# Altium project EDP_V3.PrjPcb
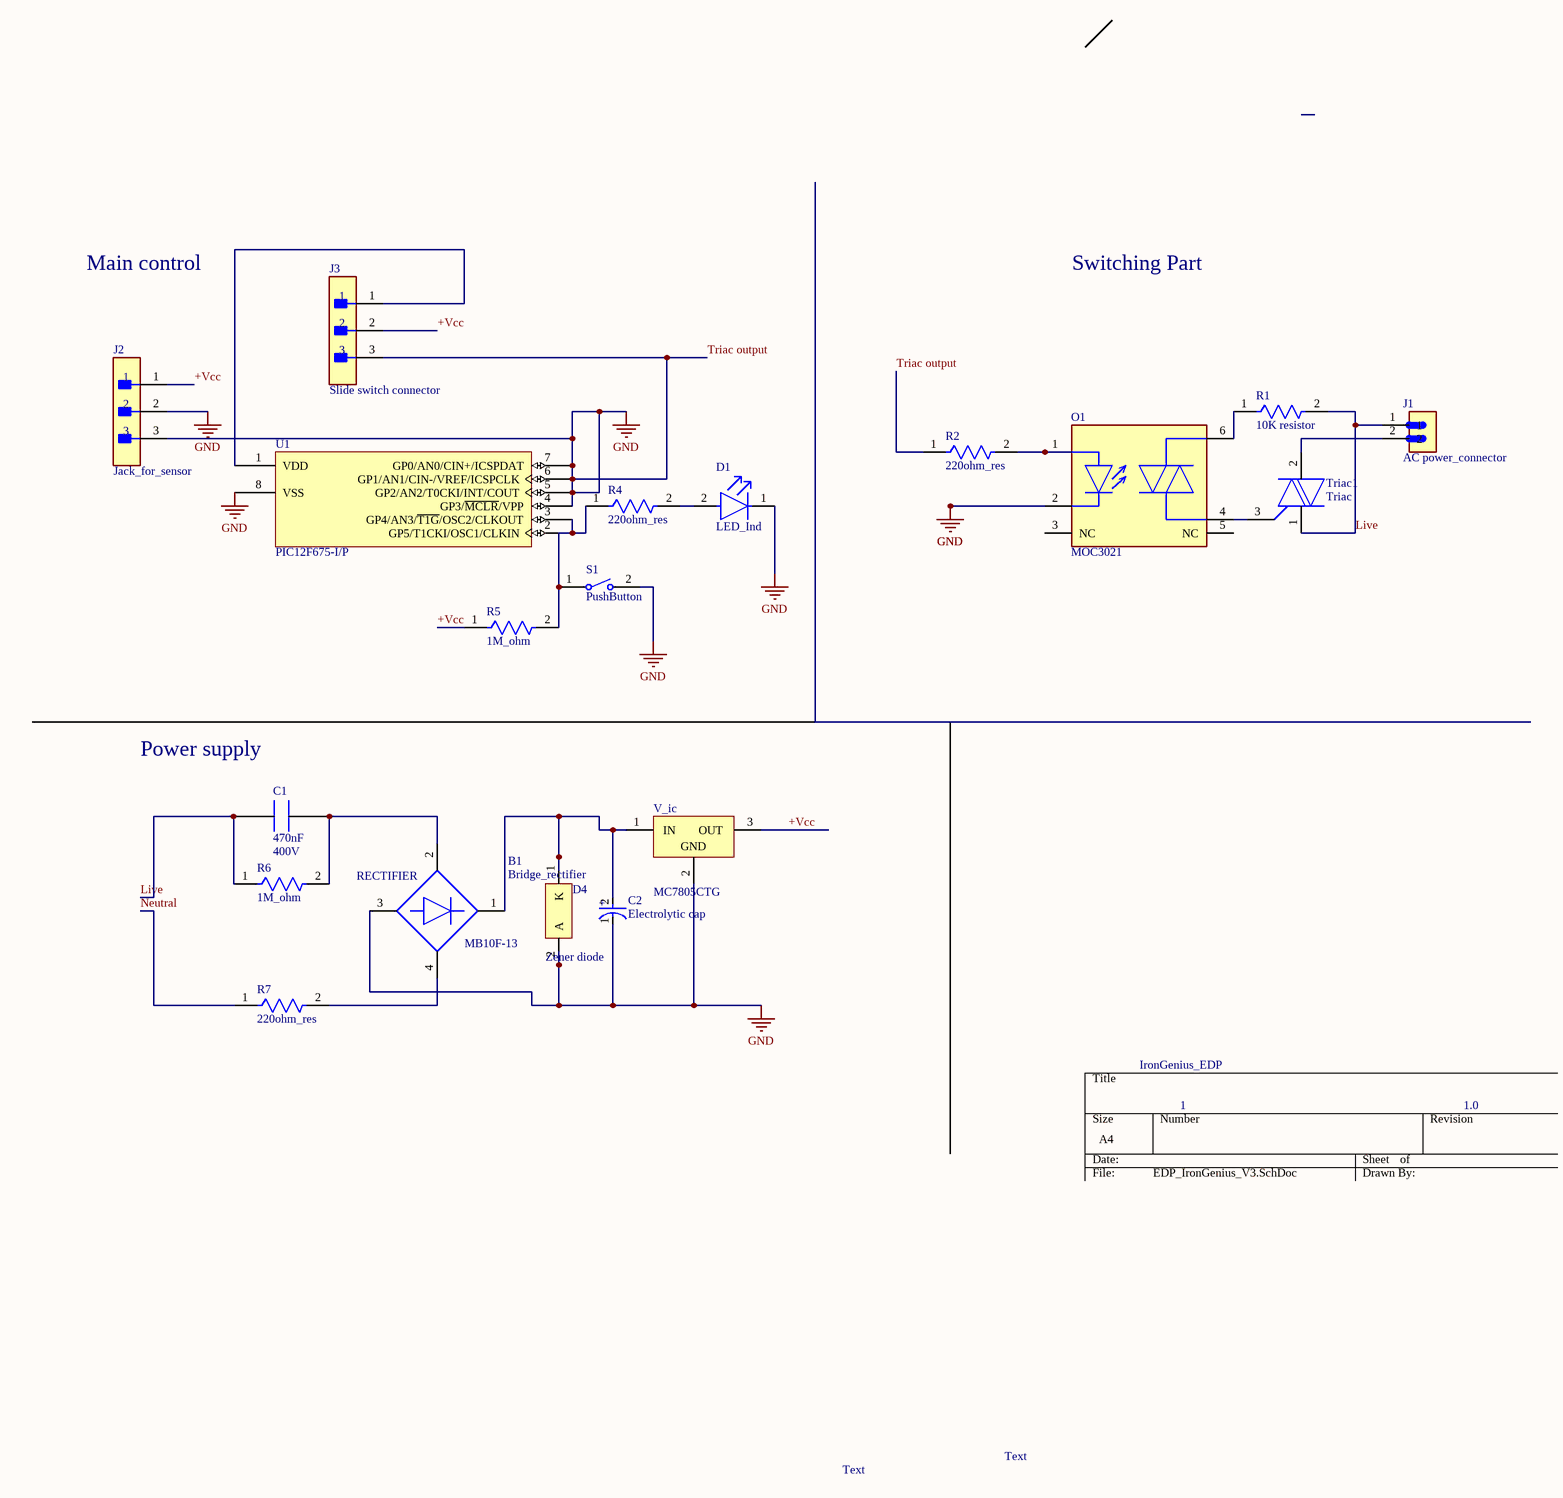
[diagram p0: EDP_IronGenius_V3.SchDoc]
1 sheet, 19 parts. Net scope: global (net labels, ports and power ports of the same name join across sheets).
Board file: EDP_V3.PcbDoc

## Sheet EDP_IronGenius_V3.SchDoc: IronGenius_EDP
size A4; Revision: 1.0; SheetNumber: 1; SheetTotal: 1

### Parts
B1  Bridge_rectifier  Manufacturer Part Number: MB10F-13  Diode Type: RECTIFIER  [Bridge rectifier]
C1  value 470nF  Rated AC Voltage (URac): 400V  [Capacitor 470nF 400V AC]
C2  Electrolytic cap  [Electrolytic cap]
D1  LED_Ind  [LED_ind]
D4  Zener diode  [Diode]
J1  AC power_connector  [AC power_connector]
J2  Jack_for_sensor  [Sensor_jack]
J3  Slide switch connector  [Sensor_jack]
O1  MOC3021  [DIP6]
R1  10K resistor  [10K resistor]
R2  220ohm_res  [220ohm_res]
R4  220ohm_res  [220ohm_res]
R5  1M_ohm  [1M_om]
R6  1M_ohm  [1M_om]
R7  220ohm_res  [220ohm_res]
S1  PushButton  [PushButton]
Triac1  Triac  [Triac BTA16-600]
U1  PIC12F675-I/P  [PDIP300-P8]
V_ic  MC7805CTG  [IC7805]

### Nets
Triac output: B1.3(-) C2.1(C) D1.1(C) D4.2(A) J2.2 J2.3 J3.3 O1.2(C) R2.1 S1.2 U1.4(GP3/~{MCLR}/VPP) U1.5(GP2/AN2/T0CKI/INT/COUT) U1.6(GP1/AN1/CIN-/VREF/ICSPCLK) U1.7(GP0/AN0/CIN+/ICSPDAT) U1.8(VSS) V_ic.2(GND)  [also labelled GND]
+Vcc: J2.1 J3.2 R5.1 V_ic.3(OUT)
Live: C1.P10 J1.1 R1.2 R6.1 Triac1.1(A1)
Neutral: R7.1
NetB1_1: B1.1(+) C2.2(A) D4.1(K) V_ic.1(IN)
NetB1_2: B1.2(1_~) C1.P9 R6.2
NetB1_4: B1.4(2_~) R7.2
NetD1_2: D1.2(A) R4.2
NetJ1_2: J1.2 Triac1.2(A2)
NetJ3_1: J3.1 U1.1(VDD)
NetO1_1: O1.1(A) R2.2
NetO1_4: O1.4(1_MAIN_TERM.) Triac1.3(G)
NetO1_6: O1.6(2_MAIN_TERM.) R1.1
NetR4_1: R4.1 R5.2 S1.1 U1.2(GP5/T1CKI/OSC1/CLKIN) U1.3(GP4/AN3/~{T1G}/OSC2/CLKOUT)

Not connected (* = marked no-connect by the designer): O1 3(NC) 5(NC)

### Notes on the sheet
- Main control
- Switching Part
- Power supply
- Text

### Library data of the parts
B1 = Bridge_rectifier: Bridge Rectifier Diode, 1 Phase, 0.8A, 1000V V(RRM), Silicon; Manufacturer: Diodes
C1 = Component_2: Film Capacitor, Polypropylene, 630V, 5% +Tol, 5% -Tol, 0.47uF, Through Hole Mount; pin to pad: P9>1 P10>2; Manufacturer: KEMET; Manufacturer Part Number: R76PR3470SE30J; Additional Feature: RATED AC VOLTAGE (V): 400
C2 = Electrolytic cap: Aluminum Electrolytic Capacitor, Polarized, Aluminum (wet), 50V, 20% +Tol, 20% -Tol, 220uF, Through Hole Mount; Manufacturer: Panasonic; Manufacturer Part Number: EEU-FR1H221B; Manufacturer Series: FR; Dielectric Material: Aluminium; Leakage Current: 110uA; Ripple Current: 1.155A; Tan Delta: 0.1
D1 = LED_Ind: Single Color LED, Yellow, Tinted Diffused, T-1, 3mm; Manufacturer: Broadcom Avago; Shape: Round; Channels: 1; Forward Current: 7mA; Forward Voltage: 2.7V; Luminous Intensity-Nom: 2.1mcd; Viewing Angle: 50°; Lens Style: Diffused,Tinted; Overall Height: 4.445mm
D4 = Diode: Rectifier Diode, 1 Phase, 1 Element, 1A, 1000V V(RRM), Silicon, DO-41; Manufacturer: ON Semiconductor; Manufacturer Part Number: 1N4007RLG; Package Body Material: Plastic; Case Connection: Isolated; Forward Voltage: 1.1V; Non-rep Pk Forward Current-Max: 30A; Number of Elements: 1; Rep Pk Reverse Voltage-Max: 1kV; Surface Mount: No; Time @ Peak Reflow Temperature-Max (s): 40s; Qualification Status: Not Qualified
J1 = AC power_connector: Barrier Strip Terminal Block, 10A, 1 Row(s), 1 Deck(s); Manufacturer: On-Shore Technology; Manufacturer Part Number: OSTTE020104; Fastening Method: SCREW; Additional Feature: STANDARD: UL 94V-0, THERMOPLASTIC; Number of Decks: 1; Number of Ways: 2; Voltage Rating: 125V; Wire/Cable Gauge: 16AWG; Safety Approval: UL,CUL
J2 J3 = Jack_for_sensor: Conn Shrouded Header (4 Sides) HDR 3 POS 2mm Solder RA Side Entry Thru-Hole Box; Manufacturer: JST; Manufacturer Part Number: S3B-PH-K-S(LF)(SN)
O1 = MOC3021: OPTOISOLATOR 4.17KV TRIAC 6DIP; Manufacturer: ON Semiconductor / Fairchild; Manufacturer Part Number: MOC3021M
R1 = 10K resistor: Fixed Resistor, Thin Film, 0.6W, 1000ohm, 350V, 1% +/-Tol, 50ppm/Cel, Through Hole Mount; Manufacturer: Vishay; Manufacturer Part Number: MRS25000C1001FCT00; Power: 600mW; Rated Temperature: 70°C; Value: 1kR; Temperature Coefficient (ppm/Cel): 50; Additional Feature: RATED AC VOLTAGE: 350V; Lead Length: 28mm; Package Length: 6.5mm; Lead Diameter: 0.6mm
R2 R4 R7 = 220ohm_res: Fixed Resistor, Metal Film, 0.25W, 220ohm, 200V, 1% +/-Tol, 50ppm/Cel, Through Hole Mount; Manufacturer: Vishay Beyschlag; Manufacturer Part Number: MBA02040C2200FC100; Power: 400mW; Rated Temperature: 70°C; Value: 220R; Temperature Coefficient (ppm/Cel): 50; Package Length: 3.6mm; Lead Diameter: 0.5mm; Lead Length: 29mm; Reference Standard: AEC-Q200
R5 R6 = 1M_ohm: Fixed Resistor, Metal Film, 0.5W, 1000000ohm, 3500V, 1% +/-Tol, 200ppm/Cel, Through Hole Mount; Manufacturer: Vishay BCcomponents; Manufacturer Part Number: HVR3700001004FR500; Power: 500mW; Rated Temperature: 70°C; Value: 1MR; Temperature Coefficient (ppm/Cel): 200; Working Voltage: 3.5kV; Lead Length: 20.25mm; Package Length: 12mm; Lead Diameter: 0.78mm
S1 = PushButton: Keypad Switch, 1 Switches, SPST, Momentary, 0.05A, 24VDC, 2.06N, 4 PCB Hole Cnt, Solder Terminal, Through Hole-straight; Manufacturer: TE Connectivity; Manufacturer Part Number: 2-1825910-7; End Contact Plating: Silver; Actuator Color: Black; End Contact Material: Copper Alloy; Actuator Material: Nylon; Contact Current(DC)-Max: 50mA; Contact DC Max Rating R Load: .05A@24VDC; Contact Voltage(DC)-Max: 24V; Circuit Configuration: 1X1; Number of Switches: 1; Actuator Angle: 0°; Contact Function: OFF-(ON); Contact Resistance: 0.1mR; Dielectric Withstand Volts: 500VACV; Insulation Resistance: 100MR; PCB Hole Count: 4; Actuator Travel: 0.254mm; Body Breadth: 5.99mm; Body Height: 3.61mm; Actuator Length: 0.37inch
Triac1 = Triac: Snubberless TRIAC, 600V V(DRM), 16A I(T)RMS, TO-220AB; Manufacturer: STMicroelectronics; Manufacturer Part Number: BTA16-600CWRG; Package Body Material: Plastic; Case Connection: Isolated; Hold Current: 35mA; Leakage Current-Max: 2mA; Number of Elements: 1; Surface Mount: No; Additional Feature: UL RECOGNIZED; Qualification Status: Not Qualified
U1 = CMP-0190-00021-1: RISC Microcontroller, 8-Bit, FLASH, PIC CPU, 20MHz, CMOS, PDIP8; Manufacturer: Microchip; Note1: Refer to data sheet (DS41190F) for details of supply voltage range under different conditions.; Package Body Material: Plastic; Number of I/O Lines: 6; Power Supplies: 2.5; Max Supply Current: 15mA; Max Supply Voltage: 5.5V; Min Supply Voltage: 4.5V; Nominal Supply Voltage: 5V; Surface Mount: No; Peripherals: POR,WDT; Package Equivalence Code: DIP8,.3; Qualification Status: Not Qualified
V_ic = MC7805CTG: Fixed Positive Standard Regulator, 5VBIPolar; Manufacturer: ON Semiconductor; Dropout Voltage1-Nom: 2V; Input Voltage Absolute-Max: 35V; Max Supply Voltage: 20V; Min Input Voltage: 7.5V; Channels: 1; Output Current1-Max: 1A; Output Voltage1-Max: 5.25V; Output Voltage1-Min: 4.75V; Output Voltage1-Nom: 5V; Regulator Type: FIXED POSITIVE SINGLE OUTPUT STANDARD REGULATOR; Surface Mount: No; Voltage Tolerance-Max: 5%; Package Equivalence Code: SIP3,.1TB; Time @ Peak Reflow Temperature-Max (s): 40s; Qualification Status: Not Qualified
